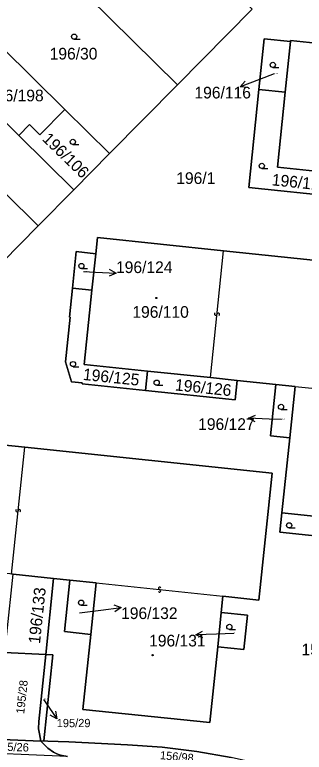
# Model space of a CAD drawing. Extents: x -598233 to -596890, y -1157848 to -1156431.
# Drawn here: x -597843.9 to -597801.7, y -1156807.5 to -1156700.1 of the extents above; entities that cross this region are included whole.
import ezdxf

# ---------------------------------------------------------------- set-up
doc = ezdxf.new("R2010")
doc.units = 0
for name, color, linetype in [('Level 1', 7, 'Continuous'), ('Level 13', 7, 'Continuous'), ('Level 3', 7, 'Continuous'), ('Level 4', 7, 'Continuous'), ('Level 5', 7, 'Continuous'), ('Level 57', 7, 'Continuous'), ('Level 60', 7, 'Continuous')]:
    doc.layers.add(name, color=color, linetype=linetype)

msp = doc.modelspace()

# ---------------------------------------------------------------- linework, layer by layer
at = {"layer": 'Level 1'}
for points in [[(-597839.74, -1156690.97), (-597820.17, -1156710.3)], [(-597809.29, -1156699.28), (-597820.17, -1156710.3)], [(-597808.32, -1156710.99), (-597807.54, -1156703.6), (-597803.73, -1156704.01)], [(-597845.75, -1156704.82), (-597836.57, -1156713.91)], [(-597804.5, -1156711.39), (-597803.73, -1156704.01)], [(-597803.73, -1156704.01), (-597803.71, -1156703.85), (-597785.3, -1156705.78)], [(-597843.29, -1156717.66), (-597852.25, -1156708.81)], [(-597820.17, -1156710.3), (-597830.07, -1156720.32)], [(-597808.32, -1156710.99), (-597809.81, -1156725.24), (-597796.75, -1156726.6)], [(-597804.5, -1156711.39), (-597808.32, -1156710.99)], [(-597860.03, -1156711.52), (-597840.47, -1156730.84)], [(-597796.4, -1156723.28), (-597805.64, -1156722.31), (-597804.5, -1156711.39)], [(-597836.57, -1156713.91), (-597840.2, -1156717.6), (-597841.72, -1156716.08), (-597843.29, -1156717.66)], [(-597836.57, -1156713.91), (-597830.07, -1156720.32)], [(-597835.27, -1156725.58), (-597843.29, -1156717.66)], [(-597830.07, -1156720.32), (-597835.27, -1156725.58)], [(-597840.47, -1156730.84), (-597835.27, -1156725.58)], [(-597840.47, -1156730.84), (-597845.67, -1156736.11)], [(-597813.46, -1156734.47), (-597831.85, -1156732.55), (-597832.09, -1156734.89)], [(-597835.48, -1156739.91), (-597834.92, -1156734.59), (-597832.09, -1156734.89)], [(-597832.65, -1156740.21), (-597832.09, -1156734.89)], [(-597813.46, -1156734.47), (-597783.65, -1156737.59)], [(-597824.85, -1156754.8), (-597834.05, -1156753.84), (-597834.04, -1156753.71), (-597835.6, -1156753.55), (-597836.48, -1156750.64), (-597835.8, -1156744.13), (-597835.92, -1156744.12), (-597835.48, -1156739.91)], [(-597832.65, -1156740.21), (-597835.48, -1156739.91)], [(-597832.65, -1156740.21), (-597833.78, -1156751.01), (-597824.55, -1156751.97)], [(-597824.55, -1156751.97), (-597824.85, -1156754.8)], [(-597824.55, -1156751.97), (-597815.37, -1156752.93)], [(-597815.37, -1156752.93), (-597811.48, -1156753.34)], [(-597824.85, -1156754.8), (-597811.77, -1156756.17), (-597811.48, -1156753.34)], [(-597811.48, -1156753.34), (-597805.88, -1156753.92)], [(-597803.83, -1156761.7), (-597806.66, -1156761.4), (-597805.88, -1156753.92)], [(-597805.88, -1156753.92), (-597803.05, -1156754.22)], [(-597803.05, -1156754.22), (-597803.83, -1156761.7)], [(-597860.82, -1156761.15), (-597842.4, -1156763.08)], [(-597804.98, -1156772.62), (-597803.83, -1156761.7)], [(-597842.4, -1156763.08), (-597806.42, -1156766.85), (-597808.36, -1156785.31), (-597813.56, -1156784.76)], [(-597796.03, -1156776.42), (-597805.27, -1156775.45), (-597804.98, -1156772.62)], [(-597795.74, -1156773.59), (-597804.98, -1156772.62)], [(-597838.21, -1156782.18), (-597844.12, -1156781.56)], [(-597838.21, -1156782.18), (-597839.37, -1156793.24)], [(-597835.84, -1156782.43), (-597838.21, -1156782.18)], [(-597835.84, -1156782.43), (-597836.62, -1156789.91), (-597832.8, -1156790.31)], [(-597832.02, -1156782.83), (-597835.84, -1156782.43)], [(-597832.8, -1156790.31), (-597832.02, -1156782.83)], [(-597813.81, -1156787.11), (-597813.56, -1156784.76)], [(-597813.81, -1156787.11), (-597814.33, -1156792.12)], [(-597814.33, -1156792.12), (-597810.5, -1156792.52), (-597809.98, -1156787.51), (-597813.81, -1156787.11)], [(-597814.33, -1156792.12), (-597815.48, -1156803.16), (-597833.94, -1156801.23), (-597832.8, -1156790.31)], [(-597845.4, -1156792.95), (-597839.37, -1156793.24)], [(-597840.09, -1156805.85), (-597840.26, -1156804.81), (-597840.42, -1156804.05), (-597840.37, -1156803.01), (-597839.37, -1156793.24)], [(-597839.64, -1156805.81), (-597838.33, -1156793.29), (-597839.37, -1156793.24)], [(-597847.96, -1156805.51), (-597840.09, -1156805.85)], [(-597840.09, -1156805.85), (-597839.64, -1156805.81)], [(-597836.2, -1156808.1), (-597837.19, -1156807.9), (-597837.75, -1156807.71), (-597838.23, -1156807.48), (-597839.05, -1156806.89), (-597840.09, -1156805.85)], [(-597801.48, -1156809), (-597804.42, -1156809.62), (-597807.4, -1156809.34), (-597812.36, -1156808.22), (-597817.37, -1156807.35), (-597822.41, -1156806.73), (-597827.48, -1156806.37), (-597836.01, -1156805.98), (-597837.54, -1156805.91), (-597839.05, -1156805.84), (-597839.64, -1156805.81)]]:
    msp.add_lwpolyline(points, dxfattribs=at)
at = {"layer": 'Level 13'}
for centre, start, end in [((-597814.6, -1156743.68), 121.4655, 353.5635), ((-597814.24, -1156743.72), 301.2511, 173.8411), ((-597843.55, -1156772.29), 121.3734, 353.4714), ((-597843.19, -1156772.33), 301.159, 173.749), ((-597822.81, -1156783.98), 211.1897, 83.7797), ((-597822.77, -1156783.62), 31.4041, 263.5021)]:
    msp.add_arc(centre, 0.184, start, end, dxfattribs=at)
at = {"layer": 'Level 3'}
for points in [[(-597815.37, -1156752.93), (-597813.46, -1156734.47)], [(-597803.05, -1156754.22), (-597785.58, -1156755.99)], [(-597844.34, -1156781.54), (-597842.4, -1156763.08)], [(-597832.02, -1156782.83), (-597813.56, -1156784.76)]]:
    msp.add_lwpolyline(points, dxfattribs=at)
at = {"layer": 'Level 5'}
for p, q in [((-597835.23, -1156703.67), (-597834.35, -1156703.67)), ((-597806.31, -1156707.78), (-597805.44, -1156707.78)), ((-597835.41, -1156718.99), (-597834.54, -1156718.99)), ((-597807.91, -1156722.49), (-597807.04, -1156722.49)), ((-597834.17, -1156737.06), (-597833.3, -1156737.06)), ((-597835.39, -1156751.34), (-597834.52, -1156751.34)), ((-597823.21, -1156754.05), (-597822.33, -1156754.05)), ((-597805.11, -1156757.57), (-597804.23, -1156757.57)), ((-597803.93, -1156774.82), (-597803.06, -1156774.82)), ((-597834.21, -1156786.08), (-597833.33, -1156786.08)), ((-597812.63, -1156789.6), (-597811.76, -1156789.6))]:
    msp.add_line(p, q, dxfattribs=at)
for centre, radius in [((-597835.23, -1156703.29), 0.375), ((-597806.31, -1156707.4), 0.375), ((-597835.41, -1156718.61), 0.375), ((-597807.91, -1156722.11), 0.375), ((-597834.17, -1156736.68), 0.375), ((-597823.26, -1156741.34), 0.09), ((-597823.26, -1156741.34), 0.0521), ((-597835.39, -1156750.96), 0.375), ((-597823.21, -1156753.67), 0.375), ((-597805.11, -1156757.19), 0.375), ((-597803.93, -1156774.44), 0.375), ((-597834.21, -1156785.7), 0.375), ((-597812.63, -1156789.22), 0.375), ((-597823.8, -1156793.33), 0.09), ((-597823.8, -1156793.33), 0.0521)]:
    msp.add_circle(centre, radius, dxfattribs=at)
at = {"layer": 'Level 57'}
for p, q in [((-597806.11, -1156708.69), (-597808.26, -1156709.52)), ((-597808.26, -1156709.52), (-597811.06, -1156710.59)), ((-597833.87, -1156737.49), (-597832.13, -1156737.57)), ((-597832.13, -1156737.57), (-597829.13, -1156737.71)), ((-597806.85, -1156758.96), (-597809.85, -1156758.85)), ((-597805.05, -1156759.03), (-597806.85, -1156758.96)), ((-597831.36, -1156786.78), (-597828.39, -1156786.38)), ((-597834.45, -1156787.19), (-597831.36, -1156786.78)), ((-597814.51, -1156790.26), (-597817.51, -1156790.37)), ((-597811.97, -1156790.17), (-597814.51, -1156790.26)), ((-597839.71, -1156799.79), (-597839.46, -1156800.15)), ((-597839.46, -1156800.15), (-597837.76, -1156802.62))]:
    msp.add_line(p, q, dxfattribs=at)
for points in [[(-597809.95, -1156710.7), (-597811.06, -1156710.59), (-597810.31, -1156709.77)], [(-597830.11, -1156737.16), (-597829.13, -1156737.71), (-597830.15, -1156738.16)], [(-597808.87, -1156759.39), (-597809.85, -1156758.85), (-597808.83, -1156758.39)], [(-597829.45, -1156786.02), (-597828.39, -1156786.38), (-597829.32, -1156787.01)], [(-597816.49, -1156790.83), (-597817.51, -1156790.37), (-597816.53, -1156789.83)], [(-597837.92, -1156801.51), (-597837.76, -1156802.62), (-597838.74, -1156802.08)]]:
    msp.add_lwpolyline(points, dxfattribs=at)
at = {"layer": 'Level 60'}
for points in [[(-597820.17, -1156710.3), (-597839.74, -1156690.97), (-597828.86, -1156679.95), (-597826.26, -1156682.51), (-597817.31, -1156691.36), (-597813.65, -1156694.98), (-597809.29, -1156699.28)], [(-597839.74, -1156690.97), (-597820.17, -1156710.3), (-597830.07, -1156720.32), (-597836.57, -1156713.91), (-597845.75, -1156704.82), (-597849.63, -1156700.99)], [(-597840.2, -1156717.6), (-597841.72, -1156716.08), (-597843.29, -1156717.66), (-597852.25, -1156708.81), (-597854.83, -1156706.26), (-597849.63, -1156700.99), (-597845.75, -1156704.82), (-597836.57, -1156713.91)], [(-597808.32, -1156710.99), (-597807.54, -1156703.6), (-597803.73, -1156704.01), (-597804.5, -1156711.39)], [(-597796.4, -1156723.28), (-597805.64, -1156722.31), (-597804.5, -1156711.39), (-597803.73, -1156704.01), (-597803.71, -1156703.85), (-597785.3, -1156705.78), (-597764.57, -1156707.96), (-597753.71, -1156709.1), (-597755.63, -1156727.55), (-597755.87, -1156729.85), (-597756.41, -1156735.02), (-597757.52, -1156745.67), (-597757.55, -1156745.95), (-597776.01, -1156744.01), (-597774.08, -1156725.61), (-597782.31, -1156724.75), (-597784.35, -1156724.54), (-597787.25, -1156724.23)], [(-597840.47, -1156730.84), (-597860.03, -1156711.52), (-597854.83, -1156706.26), (-597852.25, -1156708.81), (-597843.29, -1156717.66), (-597835.27, -1156725.58)], [(-597809.81, -1156725.24), (-597808.32, -1156710.99), (-597804.5, -1156711.39), (-597805.64, -1156722.31), (-597796.4, -1156723.28), (-597796.75, -1156726.6)], [(-597860.03, -1156711.52), (-597840.47, -1156730.84), (-597845.67, -1156736.11), (-597865.23, -1156716.79)], [(-597830.07, -1156720.32), (-597835.27, -1156725.58), (-597843.29, -1156717.66), (-597841.72, -1156716.08), (-597840.2, -1156717.6), (-597836.57, -1156713.91)], [(-597785.58, -1156755.99), (-597784.59, -1156756.09), (-597784.84, -1156758.45), (-597785.38, -1156763.63), (-597786.52, -1156774.55), (-597795.74, -1156773.59), (-597804.98, -1156772.62), (-597803.83, -1156761.7), (-597803.05, -1156754.22), (-597805.88, -1156753.92), (-597811.48, -1156753.34), (-597815.37, -1156752.93), (-597824.55, -1156751.97), (-597833.78, -1156751.01), (-597832.65, -1156740.21), (-597832.09, -1156734.89), (-597831.85, -1156732.55), (-597813.46, -1156734.47), (-597783.65, -1156737.59), (-597784.23, -1156743.15), (-597784.97, -1156750.15)], [(-597835.48, -1156739.91), (-597834.92, -1156734.59), (-597832.09, -1156734.89), (-597832.65, -1156740.21)], [(-597824.85, -1156754.8), (-597834.05, -1156753.84), (-597834.04, -1156753.71), (-597835.6, -1156753.55), (-597836.48, -1156750.64), (-597835.8, -1156744.13), (-597835.92, -1156744.12), (-597835.48, -1156739.91), (-597832.65, -1156740.21), (-597833.78, -1156751.01), (-597824.55, -1156751.97)], [(-597811.77, -1156756.17), (-597824.85, -1156754.8), (-597824.55, -1156751.97), (-597815.37, -1156752.93), (-597811.48, -1156753.34)], [(-597803.83, -1156761.7), (-597806.66, -1156761.4), (-597805.88, -1156753.92), (-597803.05, -1156754.22)], [(-597806.42, -1156766.85), (-597808.36, -1156785.31), (-597813.56, -1156784.76), (-597813.81, -1156787.11), (-597814.33, -1156792.12), (-597815.48, -1156803.16), (-597833.94, -1156801.23), (-597832.8, -1156790.31), (-597832.02, -1156782.83), (-597835.84, -1156782.43), (-597838.21, -1156782.18), (-597844.12, -1156781.56), (-597844.34, -1156781.54), (-597844.57, -1156781.52), (-597853.53, -1156780.58), (-597862.75, -1156779.61), (-597861.61, -1156768.69), (-597860.82, -1156761.15), (-597842.4, -1156763.08)], [(-597796.03, -1156776.42), (-597805.27, -1156775.45), (-597804.98, -1156772.62), (-597795.74, -1156773.59)], [(-597845.4, -1156792.95), (-597845.03, -1156790.28), (-597844.12, -1156781.56), (-597838.21, -1156782.18), (-597839.37, -1156793.24)], [(-597836.62, -1156789.91), (-597835.84, -1156782.43), (-597832.02, -1156782.83), (-597832.8, -1156790.31)], [(-597809.98, -1156787.51), (-597810.5, -1156792.52), (-597814.33, -1156792.12), (-597813.81, -1156787.11)], [(-597846.76, -1156803.11), (-597846.71, -1156802.61), (-597845.4, -1156792.95), (-597839.37, -1156793.24), (-597840.37, -1156803.01), (-597840.42, -1156804.05), (-597840.26, -1156804.81), (-597840.09, -1156805.85), (-597847.96, -1156805.51), (-597847.45, -1156804.62), (-597847.01, -1156803.84)], [(-597840.09, -1156805.85), (-597840.26, -1156804.81), (-597840.42, -1156804.05), (-597840.37, -1156803.01), (-597839.37, -1156793.24), (-597838.33, -1156793.29), (-597839.64, -1156805.81)], [(-597851.99, -1156807.39), (-597850.45, -1156807.23), (-597849.11, -1156806.62), (-597848.35, -1156805.92), (-597847.96, -1156805.51), (-597840.09, -1156805.85), (-597839.05, -1156806.89), (-597838.23, -1156807.48), (-597837.75, -1156807.71), (-597837.19, -1156807.9), (-597836.2, -1156808.1)]]:
    msp.add_lwpolyline(points, close=True, dxfattribs=at)
for points in [[(-597845.67, -1156736.11), (-597840.47, -1156730.84), (-597835.27, -1156725.58), (-597830.07, -1156720.32), (-597820.17, -1156710.3), (-597809.29, -1156699.28)], [(-597785.3, -1156705.78), (-597803.71, -1156703.85), (-597803.73, -1156704.01), (-597807.54, -1156703.6), (-597808.32, -1156710.99), (-597809.81, -1156725.24), (-597796.75, -1156726.6)], [(-597783.65, -1156737.59), (-597813.46, -1156734.47), (-597831.85, -1156732.55), (-597832.09, -1156734.89), (-597834.92, -1156734.59), (-597835.48, -1156739.91), (-597835.92, -1156744.12), (-597835.8, -1156744.13), (-597836.48, -1156750.64), (-597835.6, -1156753.55), (-597834.04, -1156753.71), (-597834.05, -1156753.84), (-597824.85, -1156754.8), (-597811.77, -1156756.17), (-597811.48, -1156753.34), (-597805.88, -1156753.92), (-597806.66, -1156761.4), (-597803.83, -1156761.7), (-597804.98, -1156772.62), (-597805.27, -1156775.45), (-597796.03, -1156776.42)], [(-597812.36, -1156808.22), (-597817.37, -1156807.35), (-597822.41, -1156806.73), (-597827.48, -1156806.37), (-597836.01, -1156805.98), (-597837.54, -1156805.91), (-597839.05, -1156805.84), (-597839.64, -1156805.81), (-597838.33, -1156793.29), (-597839.37, -1156793.24), (-597838.21, -1156782.18), (-597835.84, -1156782.43), (-597836.62, -1156789.91), (-597832.8, -1156790.31), (-597833.94, -1156801.23), (-597815.48, -1156803.16), (-597814.33, -1156792.12), (-597810.5, -1156792.52), (-597809.98, -1156787.51), (-597813.81, -1156787.11), (-597813.56, -1156784.76), (-597808.36, -1156785.31), (-597806.42, -1156766.85), (-597842.4, -1156763.08), (-597860.82, -1156761.15)], [(-597838.23, -1156807.48), (-597839.05, -1156806.89), (-597840.09, -1156805.85), (-597839.64, -1156805.81), (-597839.05, -1156805.84), (-597837.54, -1156805.91), (-597836.01, -1156805.98), (-597827.48, -1156806.37), (-597822.41, -1156806.73), (-597817.37, -1156807.35), (-597812.36, -1156808.22)]]:
    msp.add_lwpolyline(points, dxfattribs=at)

# ---------------------------------------------------------------- texts
at = {"layer": 'Level 4'}
for s, height, p in [('196/30', 1.7, (-597838.79, -1156706.62)), ('196/116', 0.1, (-597806.11, -1156708.69)), ('196/198', 1.7, (-597847.88, -1156712.71)), ('196/1', 1.7, (-597820.36, -1156724.74)), ('196/124', 0.1, (-597833.87, -1156737.49)), ('196/110', 1.7, (-597826.75, -1156744.22)), ('196/127', 0.1, (-597805.05, -1156759.03)), ('196/132', 0.1, (-597834.45, -1156787.19)), ('196/131', 0.1, (-597811.97, -1156790.17)), ('195/29', 0.1, (-597839.71, -1156799.79))]:
    msp.add_text(s, height=height, dxfattribs=at).set_placement(p)
for s, height, rotation, p in [('196/106', 1.7, 315.9, (-597839.98, -1156718.31)), ('196/117', 1.7, 354.055, (-597806.51, -1156724.93)), ('196/125', 1.7, 354.0429, (-597834, -1156753.26)), ('196/126', 1.7, 354.0429, (-597820.6, -1156754.79)), ('196/133', 1.7, 84.0126, (-597840.2, -1156791.74)), ('195/28', 1.2, 83.7, (-597842.5, -1156801.92)), ('195/26', 1.2, 358.2, (-597846.75, -1156807.22)), ('156/98', 1.2, 354.6, (-597822.77, -1156808.47))]:
    msp.add_text(s, height=height, rotation=rotation, dxfattribs=at).set_placement(p)
at = {"layer": 'Level 57'}
for s, height, p in [('196/116', 1.7, (-597817.71, -1156712.29)), ('196/124', 1.7, (-597829.13, -1156737.71)), ('196/127', 1.7, (-597817.17, -1156760.55)), ('196/132', 1.7, (-597828.39, -1156788.08)), ('196/131', 1.7, (-597824.31, -1156792.07)), ('156/100', 1.7, (-597802.12, -1156793.36)), ('195/29', 1.2, (-597837.76, -1156803.82))]:
    msp.add_text(s, height=height, dxfattribs=at).set_placement(p)

doc.saveas('drawing.dxf')
